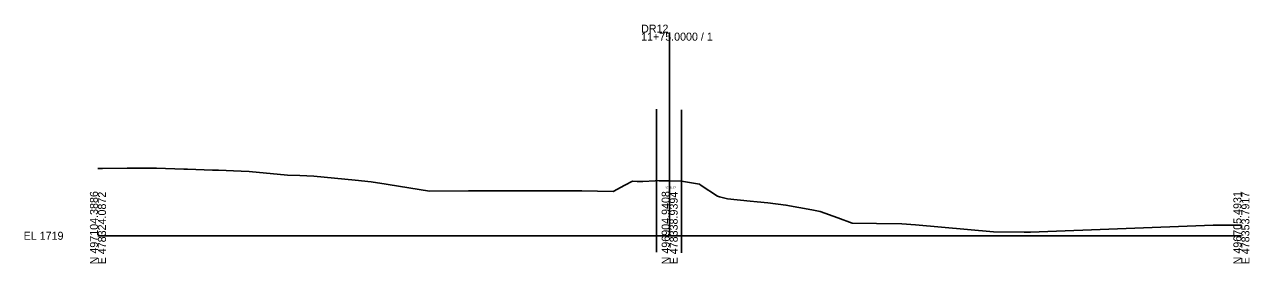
# Model space of a CAD drawing. Extents: x -26 to 403, y -10 to 3574.
# Drawn here: x -25.7 to 402.8, y 3490.3 to 3573.9 of the extents above; entities that cross this region are included whole.
import ezdxf

# ---------------------------------------------------------------- set-up
doc = ezdxf.new("R2010")
doc.units = 0
for name, color, linetype in [('Exist Cross Section Cell', 7, 'Continuous'), ('Exist XS Center Line Elevation Label', 7, 'Continuous'), ('Exist XS Ground Line', 7, 'Continuous'), ('Scratch_Level_1', 7, 'Continuous'), ('Scratch_Level_5', 7, 'Continuous')]:
    doc.layers.add(name, color=color, linetype=linetype)

msp = doc.modelspace()

# ---------------------------------------------------------------- linework, layer by layer
at = {"layer": 'Exist Cross Section Cell'}
for p, q in [((200, 3500), (200, 3571.01)), ((0, 3500), (200, 3500)), ((200, 3500), (400, 3500))]:
    msp.add_line(p, q, dxfattribs=at)
at = {"layer": 'Exist XS Ground Line'}
msp.add_lwpolyline([(0, 3523.56), (1.63, 3523.55), (10.27, 3523.67), (14.94, 3523.67), (20.03, 3523.62), (20.44, 3523.6), (30.06, 3523.32), (31.28, 3523.28), (40.09, 3522.98), (42.12, 3522.88), (50.12, 3522.61), (52.95, 3522.49), (66.32, 3521.23), (70.63, 3521.02), (75.57, 3520.81), (89.93, 3519.49), (95.58, 3518.84), (100.77, 3518.07), (101.55, 3517.95), (115.98, 3515.64), (129.63, 3515.71), (134.82, 3515.72), (141.7, 3515.68), (169.33, 3515.72), (180.19, 3515.44), (184.34, 3517.69), (187, 3519.08), (188.65, 3518.98), (190.64, 3519.02), (194.94, 3519.23), (195.39, 3519.27), (196.29, 3519.25), (200, 3519.17), (204.16, 3519.08), (209.07, 3518.27), (210.38, 3518.07), (211.07, 3517.6), (216.73, 3513.87), (217.42, 3513.63), (220.22, 3512.92), (228.15, 3512.11), (230.66, 3511.91), (234.38, 3511.47), (240.69, 3510.75), (249.78, 3509.06), (252.11, 3508.58), (252.62, 3508.5), (258.81, 3506.27), (263.9, 3504.42), (272.38, 3504.3), (281.18, 3504.18), (286.05, 3503.86), (313.24, 3501.32), (324.02, 3501.27), (326.26, 3501.26), (390.16, 3503.74), (399.69, 3503.68), (400, 3503.68)], dxfattribs=at)
at = {"layer": 'Scratch_Level_1'}
for p, q in [((195.39, 3544.27), (195.39, 3494.27)), ((204.16, 3544.08), (204.16, 3494.08))]:
    msp.add_line(p, q, dxfattribs=at)
at = {"layer": 'Scratch_Level_5'}
msp.add_lwpolyline([(0, 3523.56), (1.63, 3523.55), (10.27, 3523.67), (14.94, 3523.67), (20.03, 3523.62), (20.44, 3523.6), (30.06, 3523.32), (31.28, 3523.28), (40.09, 3522.98), (42.12, 3522.88), (50.12, 3522.61), (52.95, 3522.49), (66.32, 3521.23), (70.63, 3521.02), (75.57, 3520.81), (89.93, 3519.49), (95.58, 3518.84), (100.77, 3518.07), (101.55, 3517.95), (115.98, 3515.64), (129.63, 3515.71), (134.82, 3515.72), (141.7, 3515.68), (169.33, 3515.72), (180.19, 3515.44), (184.34, 3517.69), (187, 3519.08), (188.65, 3518.98), (190.64, 3519.02), (194.94, 3519.23), (195.39, 3519.27), (196.29, 3519.25), (200, 3519.17), (204.16, 3519.08), (209.07, 3518.27), (210.38, 3518.07), (211.07, 3517.6), (216.73, 3513.87), (217.42, 3513.63), (220.22, 3512.92), (228.15, 3512.11), (230.66, 3511.91), (234.38, 3511.47), (240.69, 3510.75), (249.78, 3509.06), (252.11, 3508.58), (252.62, 3508.5), (258.81, 3506.27), (263.9, 3504.42), (272.38, 3504.3), (281.18, 3504.18), (286.05, 3503.86), (313.24, 3501.32), (324.02, 3501.27), (326.26, 3501.26), (390.16, 3503.74), (399.69, 3503.68), (400, 3503.68)], dxfattribs=at)

# ---------------------------------------------------------------- texts
at = {"layer": 'Exist Cross Section Cell'}
for s, p in [('11+75.0000 / 1', (190, 3568.21)), ('DR12', (190, 3571.01)), ('EL 1719', (-26, 3498.6))]:
    msp.add_text(s, height=2.8, dxfattribs=at).set_placement(p)
for s, p in [('N 497104.3886', (0, 3490)), ('E 478324.0872', (2.8, 3490)), ('N 496904.9408', (200, 3490)), ('E 478338.9394', (202.8, 3490)), ('N 496705.4931', (400, 3490)), ('E 478353.7917', (402.8, 3490))]:
    msp.add_text(s, height=2.8, rotation=90, dxfattribs=at).set_placement(p)
at = {"layer": 'Exist XS Center Line Elevation Label'}
msp.add_text('1738.17', height=0.75, dxfattribs=at).set_placement((198.43, 3516.42))

doc.saveas('drawing.dxf')
